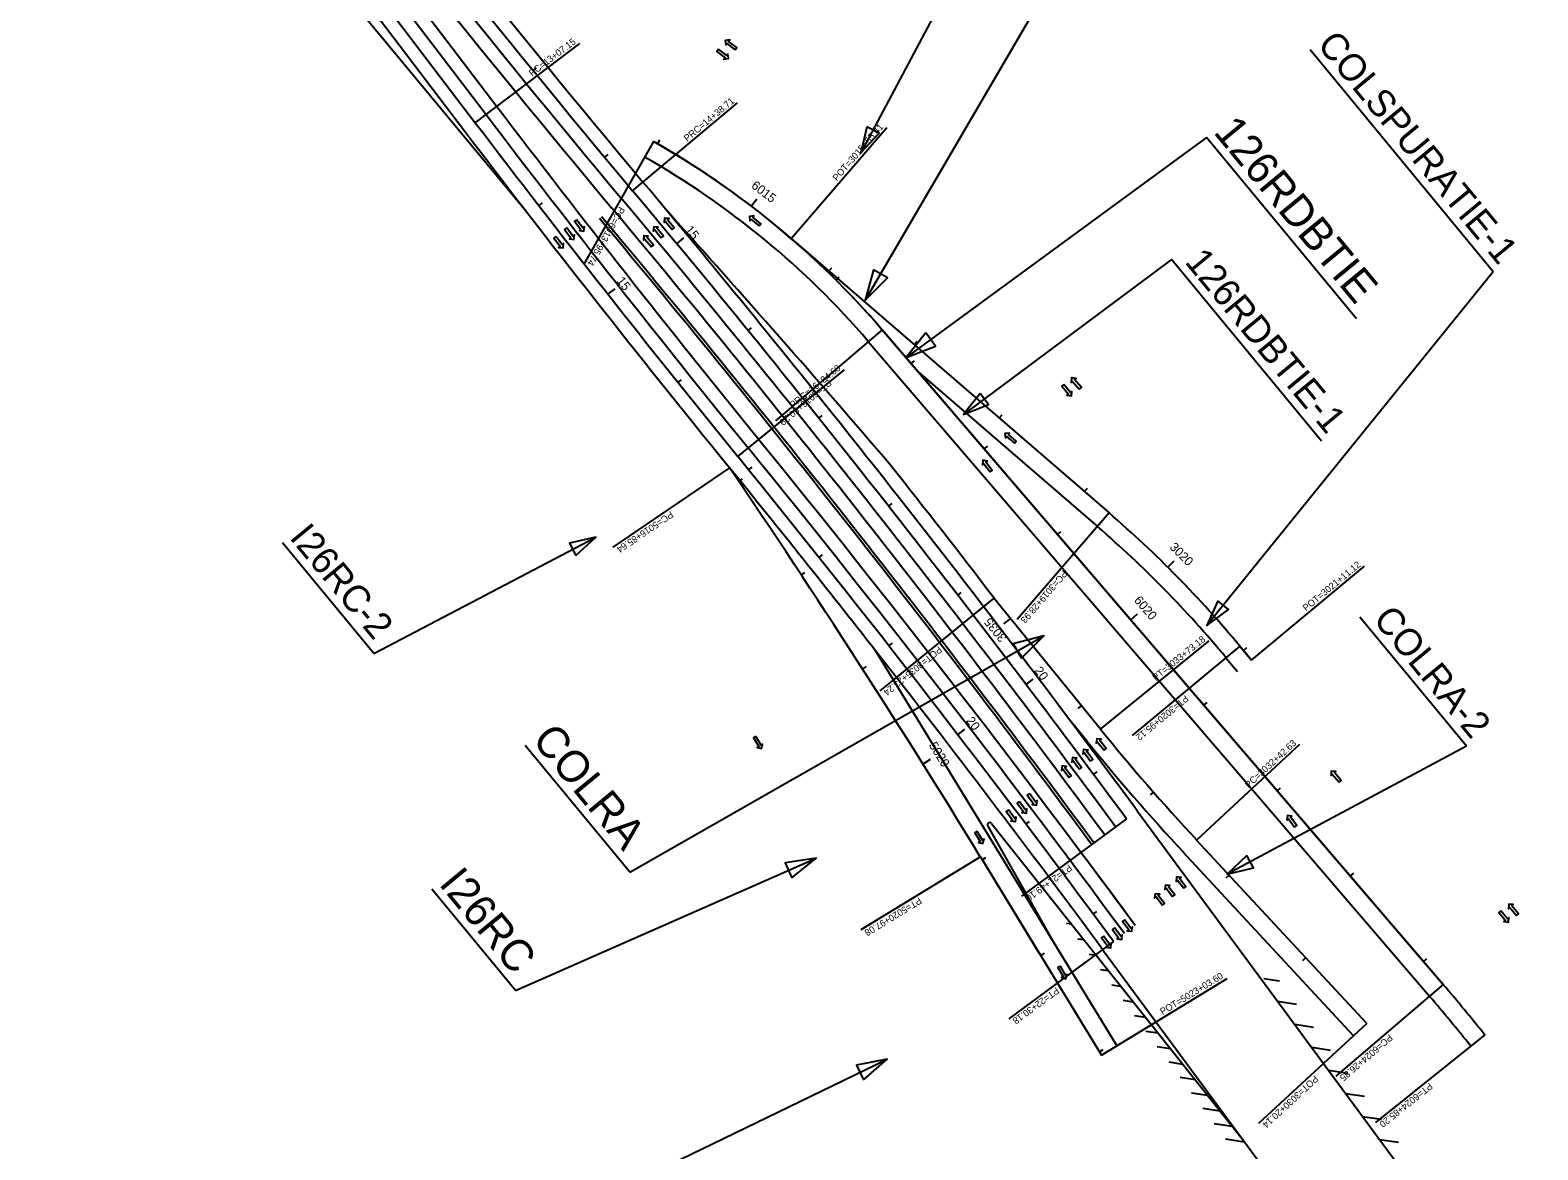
# Model space of a CAD drawing. Extents: x 1966356 to 1974207, y 790684 to 800034.
# Drawn here: x 1969541 to 1970882, y 796663 to 797658 of the extents above; entities that cross this region are included whole.
import ezdxf

# ---------------------------------------------------------------- set-up
doc = ezdxf.new("R2010")
doc.units = 0
for name, color, linetype in [('RD_EX_Pavement_Markings', 7, 'Continuous'), ('RD_HC_Cl', 7, 'Continuous'), ('RD_HC_Data', 7, 'Continuous'), ('RD_HC_Data_Tic', 7, 'Continuous'), ('RD_HC_TX_Sta50', 7, 'Continuous'), ('RD_PD_ALT5_LnLine', 7, 'Continuous'), ('RD_TX_RoadID', 7, 'Continuous'), ('TR_WZ_Temp Conc Barrier', 7, 'Continuous')]:
    doc.layers.add(name, color=color, linetype=linetype)

msp = doc.modelspace()

# ---------------------------------------------------------------- linework, layer by layer
at = {"layer": 'RD_EX_Pavement_Markings'}
for p, q in [((1969562.5, 798108.2), (1969956.2, 797590.2)), ((1969543.4, 798093.7), (1969937.1, 797575.7)), ((1969553, 798100.9), (1969946.6, 797583))]:
    msp.add_line(p, q, dxfattribs=at)
at = {"layer": 'RD_HC_Cl'}
for p, q in [((1970217.7, 797472.9), (1970500.4, 797228.9)), ((1970298.6, 797391.7), (1970797.4, 796809.7)), ((1970492.7, 797036.7), (1970398.1, 797153.2)), ((1970616.6, 797110.3), (1970626.9, 797098)), ((1970729.4, 796774.8), (1970578.2, 796938)), ((1970386, 796923), (1970493.6, 796746.7))]:
    msp.add_line(p, q, dxfattribs=at)
for centre, radius, start, end in [((1978894.5, 804897.7), 11500, 217.23533, 219.93701), ((1979092.9, 804534.3), 11500, 217.23533, 219.11586), ((1969718.5, 796894.7), 763.9, 40.5931, 60.4341), ((1961259.3, 790132.9), 11500, 36.39766, 39.93701), ((1961247.8, 790023.8), 11500, 36.39766, 39.11586), ((1963181.8, 792526), 8440, 31.39766, 34.19078), ((1969847, 796471.9), 1000, 39.6755, 49.1974), ((1972045.7, 798296.9), 2000, 219.0581, 222.7981), ((1969544.4, 795736), 1650, 38.5668, 40.5931)]:
    msp.add_arc(centre, radius, start, end, dxfattribs=at)
at = {"layer": 'RD_HC_Data'}
for p, q in [((1969937.1, 797575.7), (1970029.9, 797646.3)), ((1970076.9, 797515.3), (1970170, 797593.3)), ((1970217.7, 797472.9), (1970302.8, 797571.5)), ((1970095.4, 797559.1), (1970033.5, 797450)), ((1970298.6, 797391.7), (1970204, 797310.7)), ((1970170.3, 797279), (1970265.1, 797356)), ((1970163.1, 797268.9), (1970059.4, 797198.4)), ((1970500.4, 797228.9), (1970418.6, 797134)), ((1970626.9, 797098), (1970727.5, 797181.5)), ((1970398.1, 797153.2), (1970296.5, 797070.7)), ((1970492.7, 797036.7), (1970589.4, 797115.1)), ((1970616.6, 797110.3), (1970520.9, 797030.9)), ((1970578.2, 796938), (1970670.1, 797023.2)), ((1970515.8, 796956.9), (1970422.7, 796888.2)), ((1970386, 796923), (1970279.7, 796858.1)), ((1970504.4, 796847.7), (1970411.2, 796779)), ((1970493.6, 796746.7), (1970605.3, 796814.9)), ((1970797.4, 796809.7), (1970702.1, 796728)), ((1970729.4, 796774.8), (1970633.3, 796685.9)), ((1970834.5, 796764.7), (1970737.2, 796687))]:
    msp.add_line(p, q, dxfattribs=at)
at = {"layer": 'RD_HC_Data_Tic'}
for p, q in [((1969988.5, 797622.2), (1969991.6, 797624.7)), ((1970099.1, 797557), (1970101.1, 797560.5)), ((1970052.1, 797545), (1970055.2, 797547.6)), ((1969993.5, 797502), (1969996.7, 797504.5)), ((1970182.3, 797501.7), (1970187.2, 797508)), ((1970116.1, 797468.2), (1970122.3, 797473.3)), ((1970251.4, 797443.8), (1970254.1, 797446.8)), ((1970257.6, 797435.9), (1970260.4, 797438.8)), ((1970055, 797423.2), (1970061.3, 797428.1)), ((1970179.6, 797390.9), (1970182.7, 797393.4)), ((1970327.1, 797378.5), (1970329.8, 797381.5)), ((1970324.4, 797361.6), (1970327.5, 797364.2)), ((1970117.2, 797344.8), (1970120.3, 797347.3)), ((1970242.3, 797313.1), (1970245.5, 797315.6)), ((1970402.8, 797313.1), (1970405.4, 797316.1)), ((1970389.5, 797285.7), (1970392.5, 797288.3)), ((1970171.2, 797257), (1970174.5, 797259.2)), ((1970180, 797267.1), (1970183.2, 797269.6)), ((1970478.5, 797247.8), (1970481.1, 797250.8)), ((1970304.4, 797234.7), (1970307.6, 797237.2)), ((1970454.6, 797209.7), (1970457.6, 797212.3)), ((1970242.7, 797189.1), (1970245.8, 797191.6)), ((1970552.5, 797180.5), (1970558.2, 797186.2)), ((1970226.8, 797173.8), (1970230.1, 797176)), ((1970365.9, 797155.8), (1970369, 797158.2)), ((1970519.6, 797133.8), (1970525.7, 797139)), ((1970412.8, 797135.1), (1970406.6, 797130.1)), ((1970304.7, 797110.6), (1970307.8, 797113.1)), ((1970619.8, 797106.6), (1970622.8, 797109.1)), ((1970281.3, 797090), (1970284.7, 797092.2)), ((1970426.6, 797076.3), (1970433, 797081.1)), ((1970584.7, 797057.8), (1970587.7, 797060.4)), ((1970475.8, 797057.5), (1970472.7, 797055)), ((1970365.9, 797031.6), (1970372.3, 797036.5)), ((1970334.9, 797005.6), (1970341.7, 797009.8)), ((1970486.6, 796996.3), (1970489.8, 796998.7)), ((1970539.8, 796980.7), (1970536.8, 796978.1)), ((1970649.8, 796981.9), (1970652.8, 796984.5)), ((1970426.5, 796952.1), (1970429.7, 796954.5)), ((1970387.5, 796920.5), (1970390.9, 796922.6)), ((1970607.2, 796906.8), (1970604.2, 796904)), ((1970714.8, 796906), (1970717.9, 796908.6)), ((1970486.4, 796872), (1970489.6, 796874.4)), ((1970439.6, 796835.2), (1970443, 796837.3)), ((1970675.1, 796833.4), (1970672.2, 796830.7)), ((1970779.9, 796830), (1970782.9, 796832.6)), ((1970491.7, 796749.8), (1970495.1, 796751.9))]:
    msp.add_line(p, q, dxfattribs=at)
at = {"layer": 'RD_PD_ALT5_LnLine'}
for p, q in [((1969534, 798086.5), (1969927.6, 797568.6)), ((1969982.7, 797496.4), (1969798.5, 797718.6)), ((1970217.7, 797472.9), (1970500.4, 797228.9)), ((1970286.4, 797381.3), (1970785.2, 796799.2)), ((1970330.8, 797354.2), (1970298.6, 797391.7)), ((1970330.8, 797354.2), (1970490, 797216.7)), ((1970797.4, 796809.7), (1970330.8, 797354.2)), ((1970492.7, 797036.7), (1970398.1, 797153.2)), ((1970292.9, 797106.1), (1970335.7, 797036)), ((1970604.3, 797100.1), (1970614.5, 797087.8)), ((1970626.9, 797098), (1970616.6, 797110.3)), ((1970480.3, 797026.6), (1970464.1, 797046.5)), ((1970335.7, 797036), (1970507.2, 796755.1)), ((1970395.9, 796952.8), (1970619.8, 796670.9)), ((1970525.5, 796964), (1970581.2, 796888.4)), ((1970392.6, 796950.5), (1970451.7, 796846)), ((1970729.4, 796774.8), (1970578.2, 796938)), ((1970717.6, 796763.9), (1970566.4, 796927.2)), ((1970386, 796923), (1970438, 796837.7)), ((1970386, 796923), (1970493.6, 796746.7)), ((1970581.2, 796888.4), (1971243.9, 795989.5)), ((1970462.5, 796864), (1970466.9, 796863.4)), ((1970472.6, 796850.3), (1970477.9, 796849.5)), ((1970482.7, 796836.6), (1970488.9, 796835.7)), ((1970494.7, 796840.6), (1970619.8, 796670.9)), ((1970492.8, 796823), (1970499.9, 796821.9)), ((1970502.9, 796809.3), (1970510.9, 796808)), ((1970637.9, 796814.8), (1970651.9, 796812.7)), ((1970513, 796795.6), (1970521.9, 796794.2)), ((1970650.2, 796794.8), (1970667, 796792.2)), ((1970523.1, 796781.9), (1970532.9, 796780.4)), ((1970533.2, 796768.2), (1970543.8, 796766.5)), ((1970665.4, 796774.3), (1970682.1, 796771.7)), ((1970543.3, 796754.5), (1970554.8, 796752.7)), ((1970680.5, 796753.8), (1970697.2, 796751.2)), ((1970553.4, 796740.8), (1970565.8, 796738.9)), ((1970563.5, 796727.1), (1970576.8, 796725)), ((1970695.6, 796733.3), (1970712.3, 796730.8)), ((1970573.6, 796713.4), (1970587.8, 796711.2)), ((1970710.7, 796712.8), (1970727.4, 796710.3)), ((1970583.7, 796699.7), (1970598.8, 796697.4)), ((1970593.8, 796686), (1970609.8, 796683.5)), ((1970725.8, 796692.3), (1970742.6, 796689.8)), ((1970603.9, 796672.3), (1970620.7, 796669.7)), ((1970619.8, 796670.9), (1971167.2, 795928.4)), ((1970740.9, 796671.8), (1970757.7, 796669.3))]:
    msp.add_line(p, q, dxfattribs=at)
for points in [[(1970168, 797640.6), (1970169.5, 797642.5), (1970162.2, 797648.1), (1970163.2, 797649.4), (1970159.2, 797648.8), (1970159.8, 797644.9), (1970160.7, 797646.2)], [(1970153.3, 797641), (1970151.8, 797639.1), (1970159.1, 797633.5), (1970158.1, 797632.3), (1970162.1, 797632.8), (1970161.6, 797636.7), (1970160.6, 797635.4)], [(1970027.1, 797489.5), (1970025.3, 797488.1), (1970030.9, 797480.8), (1970029.6, 797479.8), (1970033.6, 797479.3), (1970034.1, 797483.3), (1970032.8, 797482.3)], [(1970112, 797480.9), (1970113.9, 797482.4), (1970108, 797489.5), (1970109.3, 797490.5), (1970105.3, 797490.9), (1970104.9, 797486.9), (1970106.2, 797487.9)], [(1970189.4, 797484.1), (1970190.9, 797486), (1970183.7, 797491.7), (1970184.7, 797492.9), (1970180.7, 797492.5), (1970181.2, 797488.5), (1970182.2, 797489.8)], [(1970008.7, 797474.7), (1970006.8, 797473.2), (1970012.4, 797465.9), (1970011.1, 797464.9), (1970015.1, 797464.4), (1970015.6, 797468.4), (1970014.3, 797467.4)], [(1970018.3, 797482.3), (1970016.4, 797480.8), (1970022, 797473.5), (1970020.7, 797472.5), (1970024.7, 797472), (1970025.2, 797476), (1970023.9, 797475)], [(1970093.6, 797465.3), (1970095.4, 797466.8), (1970089.6, 797473.9), (1970090.8, 797474.9), (1970086.9, 797475.3), (1970086.5, 797471.3), (1970087.7, 797472.3)], [(1970102.4, 797473.3), (1970104.3, 797474.8), (1970098.4, 797481.9), (1970099.7, 797482.9), (1970095.7, 797483.3), (1970095.3, 797479.3), (1970096.6, 797480.4)], [(1970460.2, 797343), (1970458.4, 797341.5), (1970464.2, 797334.4), (1970462.9, 797333.4), (1970466.9, 797333), (1970467.3, 797336.9), (1970466, 797335.9)], [(1970473.9, 797338.8), (1970475.8, 797340.4), (1970469.8, 797347.4), (1970471.1, 797348.4), (1970467.1, 797348.8), (1970466.8, 797344.8), (1970468, 797345.8)], [(1970416.3, 797290.8), (1970417.8, 797292.6), (1970410.9, 797298.5), (1970411.9, 797299.8), (1970407.9, 797299.5), (1970408.3, 797295.5), (1970409.3, 797296.7)], [(1970394.6, 797265.3), (1970396.5, 797266.7), (1970391, 797274.1), (1970392.3, 797275), (1970388.3, 797275.6), (1970387.8, 797271.6), (1970389.1, 797272.6)], [(1970186.3, 797030.2), (1970184.3, 797028.9), (1970189.1, 797021.1), (1970187.7, 797020.2), (1970191.5, 797019.3), (1970192.5, 797023.2), (1970191.1, 797022.3)], [(1970484, 797008.1), (1970485.9, 797009.6), (1970480.4, 797016.9), (1970481.7, 797017.9), (1970477.8, 797018.5), (1970477.2, 797014.5), (1970478.5, 797015.5)], [(1970496.1, 797018), (1970497.9, 797019.5), (1970492.1, 797026.6), (1970493.3, 797027.6), (1970489.4, 797028), (1970489, 797024), (1970490.2, 797025)], [(1970474, 797001.1), (1970475.9, 797002.5), (1970470.4, 797009.8), (1970471.7, 797010.8), (1970467.8, 797011.4), (1970467.2, 797007.4), (1970468.5, 797008.4)], [(1970464.8, 796993.5), (1970466.7, 796995), (1970461.2, 797002.3), (1970462.5, 797003.3), (1970458.6, 797003.9), (1970458, 796999.9), (1970459.3, 797000.9)], [(1970704.9, 796989.5), (1970706.7, 796991.1), (1970700.7, 796998), (1970701.9, 796999), (1970697.9, 796999.3), (1970697.7, 796995.3), (1970698.9, 796996.4)], [(1970429.6, 796979.4), (1970427.6, 796977.9), (1970433.2, 796970.6), (1970431.9, 796969.6), (1970435.8, 796969.1), (1970436.4, 796973.1), (1970435.1, 796972.1)], [(1970410.9, 796964.8), (1970409, 796963.3), (1970414.5, 796956), (1970413.2, 796955), (1970417.2, 796954.5), (1970417.7, 796958.4), (1970416.4, 796957.5)], [(1970420.6, 796972.2), (1970418.7, 796970.8), (1970424.2, 796963.5), (1970422.9, 796962.5), (1970426.9, 796961.9), (1970427.4, 796965.9), (1970426.1, 796964.9)], [(1970665.3, 796949.5), (1970667.2, 796951), (1970661.7, 796958.3), (1970663, 796959.3), (1970659, 796959.9), (1970658.5, 796955.9), (1970659.8, 796956.9)], [(1970383.1, 796945.7), (1970381.1, 796944.4), (1970385.8, 796936.6), (1970384.4, 796935.8), (1970388.3, 796934.8), (1970389.3, 796938.7), (1970387.9, 796937.9)], [(1970556.9, 796887.8), (1970558.8, 796889.3), (1970553.2, 796896.5), (1970554.5, 796897.5), (1970550.5, 796898), (1970550, 796894.1), (1970551.3, 796895.1)], [(1970566.8, 796895.1), (1970568.7, 796896.5), (1970563.1, 796903.8), (1970564.4, 796904.8), (1970560.4, 796905.3), (1970559.9, 796901.3), (1970561.2, 796902.3)], [(1970547.9, 796880.1), (1970549.7, 796881.6), (1970544.1, 796888.8), (1970545.4, 796889.8), (1970541.4, 796890.3), (1970540.9, 796886.4), (1970542.2, 796887.4)], [(1970848.7, 796875.2), (1970846.9, 796873.6), (1970852.7, 796866.6), (1970851.4, 796865.5), (1970855.4, 796865.1), (1970855.8, 796869.1), (1970854.6, 796868.1)], [(1970862.5, 796871), (1970864.3, 796872.5), (1970858.3, 796879.5), (1970859.6, 796880.6), (1970855.6, 796880.9), (1970855.3, 796876.9), (1970856.5, 796878)], [(1970505.3, 796860), (1970503.4, 796858.5), (1970508.9, 796851.2), (1970507.6, 796850.2), (1970511.6, 796849.7), (1970512.1, 796853.6), (1970510.8, 796852.7)], [(1970514.2, 796867.1), (1970512.3, 796865.7), (1970517.9, 796858.4), (1970516.6, 796857.4), (1970520.5, 796856.9), (1970521.1, 796860.8), (1970519.8, 796859.8)], [(1970495.6, 796852.5), (1970493.7, 796851), (1970499.2, 796843.7), (1970497.9, 796842.7), (1970501.9, 796842.2), (1970502.4, 796846.2), (1970501.1, 796845.2)], [(1970457.1, 796825.8), (1970455, 796824.6), (1970459.5, 796816.6), (1970458.1, 796815.8), (1970461.9, 796814.7), (1970463, 796818.6), (1970461.6, 796817.8)]]:
    msp.add_lwpolyline(points, close=True, dxfattribs=at)
for centre, radius, start, end in [((1978894.5, 804897.7), 11488, 217.23533, 219.93701), ((1978894.5, 804897.7), 11512, 217.23533, 219.93701), ((1978894.5, 804897.7), 11500, 217.23533, 219.93701), ((1978894.5, 804897.7), 11524, 217.23533, 219.93701), ((1979092.9, 804534.3), 11488, 217.23533, 219.11586), ((1979092.9, 804534.3), 11476, 217.23533, 219.11586), ((1979092.9, 804534.3), 11512, 217.23533, 219.11586), ((1979092.9, 804534.3), 11500, 217.23533, 219.11586), ((1969718.5, 796894.7), 763.9, 49.1974, 60.4341), ((1969718.5, 796894.7), 747.9, 40.5931, 60.4341), ((1961259.3, 790132.9), 11500, 36.39766, 39.93701), ((1961259.3, 790132.9), 11512, 39.7701, 39.93701), ((1961259.3, 790132.9), 11488, 36.39766, 39.93701), ((1961259.3, 790132.9), 11476, 36.39766, 39.93701), ((1961259.3, 790132.9), 11512, 38.27682, 39.7701), ((1961563, 789787.4), 11508.8, 40.56466, 42.06033), ((1969718.5, 796894.7), 763.9, 40.5931, 49.1974), ((1961247.8, 790023.8), 11512, 36.39766, 39.11586), ((1961247.8, 790023.8), 11524, 36.39766, 39.11586), ((1961247.8, 790023.8), 11500, 36.39766, 39.11586), ((1961247.8, 790023.8), 11488, 39.09922, 39.11586), ((1961247.8, 790023.8), 11488, 38.06099, 39.09922), ((1963181.8, 792526), 8440, 31.39766, 34.19078), ((1961259.3, 790132.9), 11512, 36.90926, 38.27682), ((1961259.3, 790132.9), 11524, 37.53057, 38.27682), ((1969847, 796471.9), 1000, 39.6755, 49.1974), ((1969847, 796471.9), 984, 39.6755, 49.1974), ((1961247.8, 790023.8), 11488, 36.39766, 38.06099), ((1961259.3, 790132.9), 11512, 36.39766, 36.90926), ((1972045.7, 798296.9), 2000, 219.0581, 222.7981), ((1972045.7, 798296.9), 2016, 219.0581, 222.7981), ((1970394.3, 796951.5), 2, 37.1411, 211.3977), ((1961247.8, 790023.8), 11524, 36.39766, 36.80076), ((1969544.4, 795736), 1650, 38.5668, 40.5931), ((1969544.4, 795736), 1634, 38.5668, 40.5931)]:
    msp.add_arc(centre, radius, start, end, dxfattribs=at)
at = {"layer": 'RD_TX_RoadID'}
for p, q in [((1970841.9, 797443.3), (1970679.2, 797640.4)), ((1970720.2, 797401.4), (1970587.1, 797562.7)), ((1970689.3, 797292.6), (1970555.9, 797454.1)), ((1969846.9, 797104), (1969765.8, 797202.2)), ((1970818, 797021.4), (1970723.2, 797136.2)), ((1970074.5, 796909.4), (1969981.3, 797022.2)), ((1969972.8, 796804.4), (1969898.5, 796894.3))]:
    msp.add_line(p, q, dxfattribs=at)
for points in [[(1970457.1, 797715.4), (1970283.5, 797418.1)], [(1970351.6, 797683.7), (1970279.7, 797548.9)], [(1970587.1, 797562.7), (1970320, 797367.1)], [(1970555.9, 797454.1), (1970370.9, 797316.3)], [(1970841.9, 797443.3), (1970587.3, 797128.9)], [(1969846.9, 797104), (1970044.1, 797207.3)], [(1970074.5, 796909.4), (1970442.4, 797119.5)], [(1970818, 797021.4), (1970605.5, 796907.8)], [(1969972.8, 796804.4), (1970240.1, 796921.9)], [(1970080.6, 796635.4), (1970303.3, 796743.1)]]:
    msp.add_lwpolyline(points, dxfattribs=at)
for points in [[(1970285.2, 797572.2), (1970279.7, 797548.9), (1970296.1, 797566.4)], [(1970290.9, 797445.1), (1970283.5, 797418.1), (1970303.4, 797437.8)], [(1970337.5, 797388.9), (1970320, 797367.1), (1970346.1, 797377.2)], [(1970385.8, 797335.1), (1970370.9, 797316.3), (1970393.2, 797325.2)], [(1970026.4, 797191.1), (1970044.1, 797207.3), (1970020.7, 797202.1)], [(1970597, 797150.8), (1970587.3, 797128.9), (1970606.7, 797143)], [(1970422.5, 797099.8), (1970442.4, 797119.5), (1970415.3, 797112.4)], [(1970623, 796924.3), (1970605.5, 796907.8), (1970628.9, 796913.3)], [(1970218.3, 796904.4), (1970240.1, 796921.9), (1970212.5, 796917.7)], [(1970282.1, 796724.8), (1970303.3, 796743.1), (1970275.8, 796737.9)]]:
    msp.add_lwpolyline(points, close=True, dxfattribs=at)
at = {"layer": 'TR_WZ_Temp Conc Barrier'}
for radius in [11461.5, 11464]:
    msp.add_arc((1961259.3, 790132.9), radius, 36.39766, 39.93701, dxfattribs=at)

# ---------------------------------------------------------------- texts
at = {"layer": 'RD_HC_Data'}
for s, rotation, p in [('PC=13+07.15', 37.2353, (1969987.6, 797616.6)), ('PRC=14+38.71', 39.937, (1970125.5, 797558.6)), ('POT=3015+55.41', 49.1974, (1970258.6, 797523.4)), ('PC=6013+95.74', 240.4341, (1970065.1, 797501.6)), ('PRC=16+84.60', 39.1159, (1970219.5, 797321.6)), ('PT=6016+60.29', 220.5931, (1970250.5, 797347.9)), ('PC=5016+85.64', 214.1908, (1970110.5, 797230.7)), ('POT=3021+11.12', 39.6755, (1970675.6, 797141.1)), ('PC=3019+28.93', 229.1974, (1970459.5, 797178.3)), ('PT=3033+73.18', 39.0581, (1970541.9, 797079.2)), ('POT=3035+23.24', 219.0581, (1970348.9, 797110.7)), ('PT=3020+95.12', 219.6755, (1970567.9, 797067.3)), ('PC=3032+42.63', 42.7981, (1970624.5, 796983.7)), ('PT=21+49.10', 216.3977, (1970464.7, 796916.7)), ('PT=5020+97.08', 211.3977, (1970331.5, 796887.4)), ('POT=5023+03.60', 31.3977, (1970548, 796782.3)), ('PT=22+30.18', 216.3977, (1970453.2, 796807.5)), ('PC=6024+26.85', 220.5931, (1970749.3, 796765.8)), ('POT=3030+20.14', 222.7981, (1970683, 796729.2)), ('PT=6024+85.20', 218.5668, (1970785, 796722.6))]:
    msp.add_text(s, height=6, rotation=rotation, dxfattribs=at).set_placement(p)
at = {"layer": 'RD_HC_TX_Sta50'}
for s, rotation, p in [('6015', 322.6147, (1970181.7, 797518.5)), ('15', 309.6316, (1970123, 797480.3)), ('15', 308.1961, (1970062.2, 797435)), ('3020', 315.1254, (1970553.6, 797197.8)), ('6020', 310.5931, (1970522.1, 797150.9)), ('3035', 129.0581, (1970409.9, 797118.1)), ('20', 307.1405, (1970433.5, 797088.6)), ('20', 307.5445, (1970372.8, 797044)), ('5020', 302.0567, (1970339.9, 797022.2))]:
    msp.add_text(s, height=8, rotation=rotation, dxfattribs=at).set_placement(p)
at = {"layer": 'RD_TX_RoadID'}
for s, height, p in [('COLSPURATIE-1', 24, (1970684.6, 797644.8)), ('126RDBTIE', 28, (1970592.5, 797567.1)), (' 126RDBTIE-1', 24, (1970561.3, 797458.6)), ('I26RC-2 ', 24, (1969771.2, 797206.7)), (' COLRA-2', 24, (1970728.6, 797140.7)), ('COLRA ', 28, (1969986.7, 797026.7)), ('I26RC ', 28, (1969903.9, 796898.8))]:
    msp.add_text(s, height=height, rotation=309.5517, dxfattribs=at).set_placement(p)

doc.saveas('drawing.dxf')
